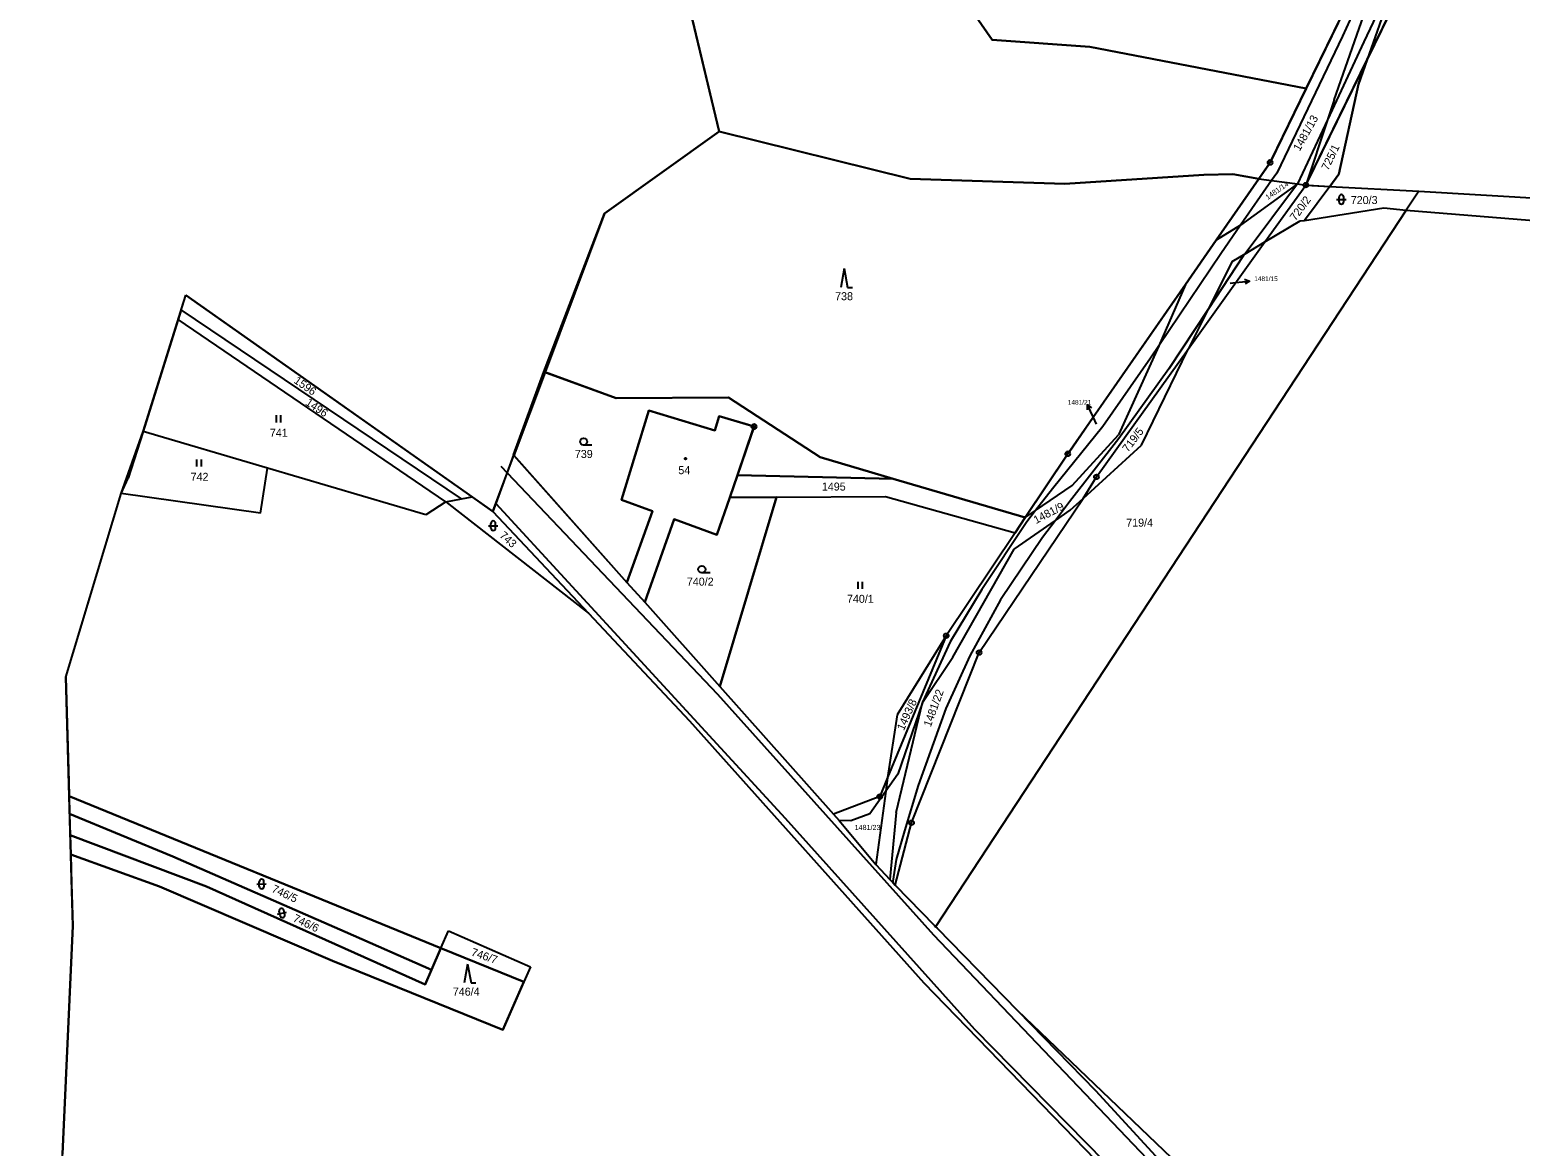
# Model space of a CAD drawing. Extents: x -760642 to -757221, y -1092371 to -1088855.
# Drawn here: x -760595.1 to -760278.5, y -1091176.2 to -1090939.2 of the extents above; entities that cross this region are included whole.
import ezdxf

# ---------------------------------------------------------------- set-up
doc = ezdxf.new("R2010")
doc.units = 0
for name, color, linetype in [('Vrstva 1', 7, 'Continuous'), ('Vrstva 13', 7, 'Continuous'), ('Vrstva 16', 7, 'Continuous'), ('Vrstva 18', 7, 'Continuous'), ('Vrstva 19', 7, 'Continuous'), ('Vrstva 24', 7, 'Continuous'), ('Vrstva 25', 7, 'Continuous'), ('Vrstva 28', 7, 'Continuous'), ('Vrstva 30', 7, 'Continuous'), ('Vrstva 4', 7, 'Continuous')]:
    doc.layers.add(name, color=color, linetype=linetype)

msp = doc.modelspace()

# ---------------------------------------------------------------- linework, layer by layer
at = {"layer": 'Vrstva 1'}
for p, q in [((-760308.9, -1090920.73), (-760324.01, -1090951.71)), ((-760318.08, -1090954.12), (-760305.91, -1090919.48)), ((-760303.79, -1090924.99), (-760311.05, -1090945.56)), ((-760311.05, -1090945.56), (-760301.6, -1090926.23)), ((-760395.84, -1090933.92), (-760390.7, -1090941.4)), ((-760390.7, -1090941.4), (-760369.95, -1090942.86)), ((-760369.95, -1090942.86), (-760324.01, -1090951.71)), ((-760324.09, -1090972.21), (-760311.05, -1090945.56)), ((-760311.05, -1090945.56), (-760312.89, -1090950.77)), ((-760324.01, -1090951.71), (-760331.67, -1090967.42)), ((-760312.89, -1090950.77), (-760317.05, -1090969.91)), ((-760318.08, -1090954.12), (-760319.48, -1090958.33)), ((-760319.48, -1090958.33), (-760324.09, -1090972.21)), ((-760448.69, -1090960.8), (-760408.07, -1090970.88)), ((-760331.67, -1090967.42), (-760334.08, -1090970.89)), ((-760408.07, -1090970.88), (-760375.23, -1090971.94)), ((-760375.23, -1090971.94), (-760345.74, -1090970.01)), ((-760345.74, -1090970.01), (-760339.59, -1090969.86)), ((-760334.08, -1090970.89), (-760343.1, -1090983.89)), ((-760339.59, -1090969.86), (-760334.08, -1090970.89)), ((-760325.86, -1090971.97), (-760337.93, -1090980.72)), ((-760334.08, -1090970.89), (-760331.36, -1090971.25)), ((-760331.36, -1090971.25), (-760325.86, -1090971.97)), ((-760325.86, -1090971.97), (-760324.09, -1090972.21)), ((-760317.05, -1090969.91), (-760318.97, -1090972.48)), ((-760332.74, -1090984.27), (-760324.09, -1090972.21)), ((-760318.97, -1090972.48), (-760324.37, -1090979.7)), ((-760324.09, -1090972.21), (-760318.97, -1090972.48)), ((-760318.97, -1090972.48), (-760300.1, -1090973.47)), ((-760300.1, -1090973.47), (-760302.77, -1090977.55)), ((-760300.1, -1090973.47), (-760272.54, -1090975.1)), ((-760302.77, -1090977.55), (-760402.7, -1091129.64)), ((-760324.37, -1090979.7), (-760307.48, -1090977.04)), ((-760307.48, -1090977.04), (-760302.77, -1090977.55)), ((-760302.77, -1090977.55), (-760270.4, -1090980.15)), ((-760337.93, -1090980.72), (-760343.1, -1090983.89)), ((-760332.74, -1090984.27), (-760325.28, -1090979.83)), ((-760325.28, -1090979.83), (-760324.37, -1090979.7)), ((-760343.1, -1090983.89), (-760349.65, -1090993.32)), ((-760349.06, -1091007.02), (-760332.74, -1090984.27)), ((-760336.96, -1090986.78), (-760332.74, -1090984.27)), ((-760339.71, -1090988.41), (-760336.96, -1090986.78)), ((-760339.71, -1090988.41), (-760344.87, -1090998.67)), ((-760349.65, -1090993.32), (-760374.62, -1091029.29)), ((-760349.65, -1090993.32), (-760355.28, -1091006.34)), ((-760503.4, -1091038.81), (-760562.9, -1090998.7)), ((-760344.87, -1090998.67), (-760349.06, -1091007.02)), ((-760506.69, -1091039.46), (-760563.55, -1091000.77)), ((-760355.28, -1091006.34), (-760363.82, -1091025.26)), ((-760368.53, -1091034.15), (-760349.06, -1091007.02)), ((-760358.95, -1091027.45), (-760349.06, -1091007.02)), ((-760485.91, -1091011.85), (-760470.52, -1091017.44)), ((-760470.52, -1091017.44), (-760446.7, -1091017.28)), ((-760446.7, -1091017.28), (-760427.2, -1091030)), ((-760463.63, -1091020.05), (-760469.4, -1091039.05)), ((-760449.58, -1091024.32), (-760463.63, -1091020.05)), ((-760448.65, -1091021.25), (-760449.58, -1091024.32)), ((-760441.26, -1091023.49), (-760448.65, -1091021.25)), ((-760544.55, -1091032.31), (-760571.02, -1091024.5)), ((-760441.26, -1091023.49), (-760444.78, -1091033.76)), ((-760373.66, -1091035.98), (-760363.82, -1091025.26)), ((-760371.37, -1091038.71), (-760358.95, -1091027.45)), ((-760492.35, -1091029.51), (-760468.24, -1091056.56)), ((-760427.2, -1091030), (-760411.7, -1091034.56)), ((-760374.62, -1091029.29), (-760383.66, -1091042.81)), ((-760546.06, -1091041.83), (-760544.55, -1091032.31)), ((-760510.92, -1091042.23), (-760544.55, -1091032.31)), ((-760444.78, -1091033.76), (-760446.42, -1091038.56)), ((-760444.78, -1091033.76), (-760411.7, -1091034.56)), ((-760411.7, -1091034.56), (-760383.66, -1091042.81)), ((-760371.37, -1091038.71), (-760368.53, -1091034.15)), ((-760546.06, -1091041.83), (-760575.65, -1091037.71)), ((-760503.4, -1091038.81), (-760501.13, -1091038.36)), ((-760436.47, -1091038.49), (-760448.53, -1091078.68)), ((-760446.42, -1091038.56), (-760436.47, -1091038.49)), ((-760436.47, -1091038.49), (-760413.36, -1091038.33)), ((-760413.36, -1091038.33), (-760385.79, -1091046)), ((-760381.47, -1091041.31), (-760373.66, -1091035.98)), ((-760506.69, -1091039.46), (-760510.92, -1091042.23)), ((-760506.69, -1091039.46), (-760503.4, -1091038.81)), ((-760506.69, -1091039.46), (-760476.43, -1091063.06)), ((-760496.71, -1091041.48), (-760476.43, -1091063.06)), ((-760469.4, -1091039.05), (-760462.84, -1091041.43)), ((-760462.84, -1091041.43), (-760468.24, -1091056.56)), ((-760446.42, -1091038.56), (-760449.12, -1091046.43)), ((-760393.47, -1091071.44), (-760371.37, -1091038.71)), ((-760383.66, -1091042.81), (-760381.47, -1091041.31)), ((-760377.23, -1091043.38), (-760374.15, -1091041.23)), ((-760374.15, -1091041.23), (-760371.37, -1091038.71)), ((-760458.18, -1091043.13), (-760464.48, -1091060.78)), ((-760458.18, -1091043.13), (-760449.12, -1091046.43)), ((-760385.98, -1091049.49), (-760377.23, -1091043.38)), ((-760383.66, -1091042.81), (-760385.79, -1091046)), ((-760385.79, -1091046), (-760400.43, -1091067.88)), ((-760399.03, -1091072.46), (-760385.98, -1091049.49)), ((-760468.24, -1091056.56), (-760464.48, -1091060.78)), ((-760476.43, -1091063.06), (-760454.93, -1091085.94)), ((-760464.48, -1091060.78), (-760448.53, -1091078.68)), ((-760400.43, -1091067.88), (-760412.88, -1091097.96)), ((-760400.43, -1091067.88), (-760410.85, -1091084.69)), ((-760407.81, -1091107.58), (-760393.47, -1091071.44)), ((-760405.51, -1091082.08), (-760399.03, -1091072.46)), ((-760448.53, -1091078.68), (-760424.37, -1091105.79)), ((-760411.08, -1091105.39), (-760405.51, -1091082.08)), ((-760454.93, -1091085.94), (-760405.18, -1091141.53)), ((-760410.85, -1091084.69), (-760412.88, -1091097.96)), ((-760412.88, -1091097.96), (-760414.57, -1091102.03)), ((-760412.88, -1091097.96), (-760413.27, -1091100.88)), ((-760413.27, -1091100.88), (-760415.37, -1091116.44)), ((-760586.71, -1091101.92), (-760507.74, -1091134.18)), ((-760414.57, -1091102.03), (-760424.37, -1091105.79)), ((-760564.71, -1091114.72), (-760586.6, -1091105.69)), ((-760424.37, -1091105.79), (-760423.19, -1091107.12)), ((-760423.19, -1091107.12), (-760415.37, -1091116.44)), ((-760411.08, -1091105.39), (-760412.39, -1091119.66)), ((-760411.28, -1091120.81), (-760407.81, -1091107.58)), ((-760586.48, -1091110.2), (-760557.56, -1091121.13)), ((-760567.52, -1091121.13), (-760586.36, -1091114.35)), ((-760564.71, -1091114.72), (-760528.07, -1091130.75)), ((-760415.37, -1091116.44), (-760412.39, -1091119.66)), ((-760412.39, -1091119.66), (-760411.81, -1091120.26)), ((-760411.81, -1091120.26), (-760411.28, -1091120.81)), ((-760530.75, -1091136.89), (-760567.52, -1091121.13)), ((-760557.56, -1091121.13), (-760511.12, -1091141.89)), ((-760411.28, -1091120.81), (-760402.9, -1091129.39)), ((-760402.9, -1091129.39), (-760402.7, -1091129.64)), ((-760402.7, -1091129.64), (-760402.34, -1091129.97)), ((-760402.34, -1091129.97), (-760385.31, -1091147.41)), ((-760528.07, -1091130.75), (-760509.75, -1091138.77)), ((-760507.74, -1091134.18), (-760506.14, -1091130.53)), ((-760506.14, -1091130.53), (-760488.73, -1091138.14)), ((-760509.75, -1091138.77), (-760507.74, -1091134.18)), ((-760507.74, -1091134.18), (-760490.14, -1091141.37)), ((-760494.58, -1091151.52), (-760530.75, -1091136.89)), ((-760509.75, -1091138.77), (-760511.12, -1091141.89)), ((-760488.73, -1091138.14), (-760490.14, -1091141.37)), ((-760490.14, -1091141.37), (-760494.58, -1091151.52)), ((-760405.18, -1091141.53), (-760373.22, -1091174.51)), ((-760334.03, -1091196.47), (-760385.31, -1091147.41)), ((-760385.31, -1091147.41), (-760368.71, -1091164.43)), ((-760368.71, -1091164.43), (-760338.69, -1091197.03)), ((-760373.22, -1091174.51), (-760347.55, -1091200.86))]:
    msp.add_line(p, q, dxfattribs=at)
at = {"layer": 'Vrstva 13'}
for p, q in [((-760464.43, -1090894.9), (-760448.69, -1090960.8)), ((-760473.02, -1090978.26), (-760448.69, -1090960.8)), ((-760485.91, -1091011.85), (-760473.02, -1090978.26)), ((-760562.9, -1090998.7), (-760561.91, -1090995.55)), ((-760501.13, -1091038.36), (-760561.91, -1090995.55)), ((-760562.9, -1090998.7), (-760563.55, -1091000.77)), ((-760563.55, -1091000.77), (-760571.02, -1091024.5)), ((-760492.35, -1091029.51), (-760485.91, -1091011.85)), ((-760571.02, -1091024.5), (-760574.15, -1091034.45)), ((-760492.35, -1091029.51), (-760496.1, -1091039.79)), ((-760575.65, -1091037.71), (-760574.15, -1091034.45)), ((-760584.51, -1091067.07), (-760575.65, -1091037.71)), ((-760496.71, -1091041.48), (-760501.13, -1091038.36)), ((-760496.1, -1091039.79), (-760496.71, -1091041.48)), ((-760587.4, -1091076.64), (-760584.51, -1091067.07)), ((-760587.4, -1091076.64), (-760586.79, -1091098.91)), ((-760586.79, -1091098.91), (-760586.71, -1091101.92)), ((-760586.71, -1091101.92), (-760586.6, -1091105.69)), ((-760586.6, -1091105.69), (-760586.48, -1091110.2)), ((-760586.48, -1091110.2), (-760586.46, -1091110.75)), ((-760586.46, -1091110.75), (-760586.36, -1091114.35)), ((-760586.36, -1091114.35), (-760586.19, -1091120.56)), ((-760586.19, -1091120.56), (-760585.95, -1091129.48)), ((-760585.95, -1091129.48), (-760588.15, -1091177.97))]:
    msp.add_line(p, q, dxfattribs=at)
at = {"layer": 'Vrstva 16'}
for p, q in [((-760340.15, -1090993.02), (-760339, -1090992.9)), ((-760339, -1090992.9), (-760336.016, -1090992.589)), ((-760369.17, -1091021.55), (-760370.435, -1091018.83)), ((-760368.5, -1091023), (-760369.17, -1091021.55))]:
    msp.add_line(p, q, dxfattribs=at)
for points in [[(-760337.063, -1090992.196), (-760336.016, -1090992.589), (-760336.959, -1090993.19)], [(-760370.467, -1091019.948), (-760370.435, -1091018.83), (-760369.56, -1091019.526)]]:
    msp.add_lwpolyline(points, dxfattribs=at)
at = {"layer": 'Vrstva 24'}
for centre, radius in [((-760331.67, -1090967.42), 0.5), ((-760331.67, -1090967.42), 0.0327), ((-760324.09, -1090972.21), 0.5), ((-760324.09, -1090972.21), 0.0327), ((-760441.26, -1091023.49), 0.5), ((-760441.26, -1091023.49), 0.0327), ((-760374.62, -1091029.29), 0.5), ((-760374.62, -1091029.29), 0.0327), ((-760368.53, -1091034.15), 0.5), ((-760368.53, -1091034.15), 0.0327), ((-760400.43, -1091067.88), 0.5), ((-760400.43, -1091067.88), 0.0327), ((-760393.47, -1091071.44), 0.5), ((-760393.47, -1091071.44), 0.0327), ((-760414.57, -1091102.03), 0.5), ((-760414.57, -1091102.03), 0.0327), ((-760407.81, -1091107.58), 0.5), ((-760407.81, -1091107.58), 0.0327)]:
    msp.add_circle(centre, radius, dxfattribs=at)
at = {"layer": 'Vrstva 25'}
for p, q in [((-760317.02, -1090975.74), (-760317.02, -1090974.74)), ((-760316.02, -1090975.74), (-760316.02, -1090974.74)), ((-760317.52, -1090975.24), (-760315.52, -1090975.24)), ((-760422.102, -1090989.939), (-760422.835, -1090993.939)), ((-760422.102, -1090989.939), (-760421.369, -1090993.939)), ((-760421.369, -1090993.939), (-760420.369, -1090993.939)), ((-760542.747, -1091021.085), (-760542.747, -1091022.585)), ((-760541.725, -1091022.585), (-760541.725, -1091021.085)), ((-760475.69, -1091027.44), (-760477.44, -1091027.44)), ((-760559.637, -1091030.445), (-760559.637, -1091031.945)), ((-760558.615, -1091031.945), (-760558.615, -1091030.445)), ((-760497.65, -1091044.52), (-760495.65, -1091044.52)), ((-760497.15, -1091045.02), (-760497.15, -1091044.02)), ((-760496.15, -1091045.02), (-760496.15, -1091044.02)), ((-760450.59, -1091054.54), (-760452.34, -1091054.54)), ((-760419.227, -1091056.455), (-760419.227, -1091057.955)), ((-760418.205, -1091057.955), (-760418.205, -1091056.455)), ((-760546.83, -1091120.611), (-760544.831, -1091120.57)), ((-760546.32, -1091121.1), (-760546.34, -1091120.101)), ((-760545.32, -1091121.08), (-760545.341, -1091120.08)), ((-760542.471, -1091126.957), (-760540.517, -1091126.529)), ((-760541.875, -1091127.338), (-760542.089, -1091126.362)), ((-760540.898, -1091127.125), (-760541.112, -1091126.148)), ((-760502.092, -1091137.569), (-760502.825, -1091141.569)), ((-760502.092, -1091137.569), (-760501.359, -1091141.569)), ((-760501.359, -1091141.569), (-760500.359, -1091141.569))]:
    msp.add_line(p, q, dxfattribs=at)
for centre, radius in [((-760477.44, -1091026.69), 0.75), ((-760455.81, -1091030.28), 0.175), ((-760452.34, -1091053.79), 0.75)]:
    msp.add_circle(centre, radius, dxfattribs=at)
for centre, start, end in [((-760316.52, -1090974.74), 0, 180), ((-760316.52, -1090975.74), 180, 0), ((-760496.65, -1091044.02), 0, 180), ((-760496.65, -1091045.02), 180, 0), ((-760545.841, -1091120.09), 1.16838, 181.16838), ((-760545.82, -1091121.09), 181.16838, 1.16838), ((-760541.601, -1091126.255), 12.33936, 192.33936), ((-760541.387, -1091127.232), 192.33936, 12.33936)]:
    msp.add_arc(centre, 0.5, start, end, dxfattribs=at)
at = {"layer": 'Vrstva 28'}
for points in [[(-760561.91, -1090995.55), (-760496.71, -1091041.48), (-760473.02, -1090978.26), (-760448.69, -1090960.8), (-760464.43, -1090894.9)], [(-760573.63, -1091420.31), (-760585.78, -1091349.95), (-760595.06, -1091293.72), (-760595.06, -1091293.72), (-760591.68, -1091230.75), (-760589.05, -1091197.58), (-760588.15, -1091177.97), (-760585.95, -1091129.48), (-760586.71, -1091101.92), (-760587.4, -1091076.64), (-760575.65, -1091037.71), (-760571.02, -1091024.5), (-760561.91, -1090995.55)]]:
    msp.add_lwpolyline(points, dxfattribs=at)
at = {"layer": 'Vrstva 30'}
for points in [[(-760483.933, -1090718.246), (-760508.9, -1090733.95), (-760505.34, -1090744.7), (-760502.31, -1090767.43), (-760480.317, -1090839.289), (-760478.97, -1090843.69), (-760473.37, -1090865.91), (-760464.43, -1090894.9), (-760448.69, -1090960.8), (-760408.07, -1090970.88), (-760375.23, -1090971.94), (-760345.74, -1090970.01), (-760339.59, -1090969.86), (-760334.08, -1090970.89), (-760331.955, -1090967.831)], [(-760301.82, -1090926.679), (-760311.05, -1090945.56), (-760312.89, -1090950.77), (-760317.05, -1090969.91), (-760318.97, -1090972.48), (-760300.1, -1090973.47), (-760272.54, -1090975.1), (-760240.96, -1090967.57), (-760199.02, -1090950.37), (-760175.7, -1090935.99), (-760191.82, -1090920.28), (-760209.38, -1090903.18), (-760217.46, -1090912.68), (-760240.32, -1090877.27), (-760234.76, -1090873.85), (-760250.43, -1090857.2), (-760274.06, -1090892.106)], [(-760395.84, -1090933.92), (-760390.7, -1090941.4), (-760369.95, -1090942.86), (-760324.01, -1090951.71), (-760309.119, -1090921.179)], [(-760331.451, -1090966.971), (-760324.01, -1090951.71), (-760369.95, -1090942.86), (-760390.7, -1090941.4), (-760395.84, -1090933.92)], [(-760323.591, -1090972.236), (-760318.97, -1090972.48), (-760317.05, -1090969.91), (-760312.89, -1090950.77), (-760311.05, -1090945.56), (-760323.87, -1090971.761)], [(-760374.335, -1091028.879), (-760369.201, -1091021.484), (-760349.65, -1090993.32), (-760343.1, -1090983.89), (-760334.08, -1090970.89), (-760339.59, -1090969.86), (-760345.74, -1090970.01), (-760375.23, -1090971.94), (-760408.07, -1090970.88), (-760448.69, -1090960.8), (-760473.02, -1090978.26), (-760485.643, -1091011.947), (-760470.52, -1091017.44), (-760446.7, -1091017.28), (-760427.2, -1091030), (-760411.7, -1091034.56), (-760383.66, -1091042.81), (-760374.898, -1091029.706)], [(-760441.422, -1091023.963), (-760444.78, -1091033.76), (-760411.7, -1091034.56), (-760427.2, -1091030), (-760446.7, -1091017.28), (-760470.52, -1091017.44), (-760485.643, -1091011.947), (-760492.262, -1091029.609), (-760468.24, -1091056.56), (-760462.84, -1091041.43), (-760469.4, -1091039.05), (-760463.63, -1091020.05), (-760449.58, -1091024.32), (-760448.65, -1091021.25), (-760441.739, -1091023.345)], [(-760441.739, -1091023.345), (-760448.65, -1091021.25), (-760449.58, -1091024.32), (-760463.63, -1091020.05), (-760469.4, -1091039.05), (-760462.84, -1091041.43), (-760468.24, -1091056.56), (-760464.48, -1091060.78), (-760458.18, -1091043.13), (-760449.12, -1091046.43), (-760446.42, -1091038.56), (-760444.78, -1091033.76), (-760441.422, -1091023.963)], [(-760411.7, -1091034.56), (-760444.78, -1091033.76), (-760446.42, -1091038.56), (-760436.47, -1091038.49), (-760413.36, -1091038.33), (-760385.79, -1091046), (-760383.66, -1091042.81), (-760411.7, -1091034.56)], [(-760448.53, -1091078.68), (-760436.47, -1091038.49), (-760446.42, -1091038.56), (-760449.12, -1091046.43), (-760458.18, -1091043.13), (-760464.48, -1091060.78), (-760448.53, -1091078.68)], [(-760507.74, -1091134.18), (-760586.71, -1091101.92), (-760586.6, -1091105.69), (-760564.71, -1091114.72), (-760528.07, -1091130.75), (-760509.75, -1091138.77), (-760507.74, -1091134.18)], [(-760509.75, -1091138.77), (-760528.07, -1091130.75), (-760564.71, -1091114.72), (-760586.6, -1091105.69), (-760586.48, -1091110.2), (-760557.56, -1091121.13), (-760511.12, -1091141.89), (-760509.75, -1091138.77)], [(-760586.482, -1091110.2), (-760586.367, -1091114.35), (-760586.36, -1091114.35), (-760567.52, -1091121.13), (-760530.75, -1091136.89), (-760494.58, -1091151.52), (-760490.14, -1091141.37), (-760507.74, -1091134.18), (-760509.75, -1091138.77), (-760511.12, -1091141.89), (-760557.56, -1091121.13), (-760586.48, -1091110.2), (-760586.482, -1091110.2)]]:
    msp.add_lwpolyline(points, dxfattribs=at)
for centre, start, end in [((-760331.67, -1090967.42), 64.00671, 180), ((-760331.67, -1090967.42), 180, 235.21907), ((-760324.09, -1090972.21), 0, 63.92723), ((-760324.09, -1090972.21), 356.98134, 0), ((-760441.26, -1091023.49), 163.1373, 180), ((-760441.26, -1091023.49), 180, 251.08106), ((-760441.26, -1091023.49), 0, 163.1373), ((-760441.26, -1091023.49), 251.08106, 0), ((-760374.62, -1091029.29), 55.23202, 180), ((-760374.62, -1091029.29), 180, 236.23177)]:
    msp.add_arc(centre, 0.5, start, end, dxfattribs=at)
at = {"layer": 'Vrstva 4'}
for p, q in [((-760307.85, -1090922.07), (-760316.26, -1090940.59)), ((-760303.79, -1090924.99), (-760311.75, -1090941.81)), ((-760316.26, -1090940.59), (-760330.26, -1090969.66)), ((-760311.75, -1090941.81), (-760319.48, -1090958.33)), ((-760319.48, -1090958.33), (-760325.86, -1090971.97)), ((-760331.36, -1090971.25), (-760337.93, -1090980.72)), ((-760325.86, -1090971.97), (-760336.96, -1090986.78)), ((-760330.26, -1090969.66), (-760331.36, -1090971.25)), ((-760337.93, -1090980.72), (-760342.15, -1090986.79)), ((-760342.15, -1090986.79), (-760355.28, -1091006.34)), ((-760337.27, -1090987.19), (-760344.87, -1090998.67)), ((-760336.96, -1090986.78), (-760337.27, -1090987.19)), ((-760344.87, -1090998.67), (-760353.16, -1091011.21)), ((-760355.28, -1091006.34), (-760357.04, -1091008.95)), ((-760357.04, -1091008.95), (-760367.18, -1091023.45)), ((-760353.16, -1091011.21), (-760363.79, -1091025.99)), ((-760367.18, -1091023.45), (-760377.87, -1091036.66)), ((-760363.79, -1091025.99), (-760374.25, -1091039.42)), ((-760495.06, -1091031.89), (-760449.04, -1091080.28)), ((-760377.87, -1091036.66), (-760381.47, -1091041.31)), ((-760496.1, -1091039.79), (-760434.62, -1091106.62)), ((-760381.47, -1091041.31), (-760383.3, -1091043.68)), ((-760374.25, -1091039.42), (-760377.23, -1091043.38)), ((-760383.3, -1091043.68), (-760392.87, -1091058.09)), ((-760377.23, -1091043.38), (-760379.96, -1091047.01)), ((-760379.96, -1091047.01), (-760388.92, -1091060.28)), ((-760392.87, -1091058.09), (-760399.6, -1091069.18)), ((-760388.92, -1091060.28), (-760395.45, -1091072.12)), ((-760399.6, -1091069.18), (-760405.47, -1091082)), ((-760395.45, -1091072.12), (-760400.54, -1091083.3)), ((-760449.04, -1091080.28), (-760403.15, -1091131.37)), ((-760405.51, -1091082.08), (-760410.72, -1091097.3)), ((-760405.47, -1091082), (-760405.51, -1091082.08)), ((-760400.54, -1091083.3), (-760406.39, -1091099.7)), ((-760410.72, -1091097.3), (-760413.27, -1091100.88)), ((-760413.27, -1091100.88), (-760416.68, -1091105.66)), ((-760406.39, -1091099.7), (-760409.3, -1091109.33)), ((-760434.62, -1091106.62), (-760394.44, -1091151.43)), ((-760420.7, -1091107.18), (-760423.19, -1091107.12)), ((-760416.68, -1091105.66), (-760420.7, -1091107.18)), ((-760409.3, -1091109.33), (-760411.1, -1091115.39)), ((-760411.1, -1091115.39), (-760411.77, -1091120.01)), ((-760411.77, -1091120.01), (-760411.81, -1091120.26)), ((-760403.15, -1091131.37), (-760341.27, -1091196.2)), ((-760394.44, -1091151.43), (-760346.69, -1091199.91))]:
    msp.add_line(p, q, dxfattribs=at)

# ---------------------------------------------------------------- texts
at = {"layer": 'Vrstva 16'}
for s, p in [('1481/15', (-760335.02, -1090992.59)), ('1481/21', (-760374.625, -1091018.83))]:
    msp.add_text(s, height=1, dxfattribs=at).set_placement(p)
at = {"layer": 'Vrstva 18'}
for s, height, rotation, p in [('1481/13', 1.7, 60.71859, (-760325.375, -1090965.147)), ('725/1', 1.7, 64.11969, (-760319.33, -1090969.22)), ('1481/14', 1.1, 34.72866, (-760332.152, -1090975.379)), ('720/2', 1.7, 53.63082, (-760326.25, -1090979.93)), ('1596', 1.7, 325.07433, (-760539.124, -1091014.077)), ('1496', 1.7, 326.30994, (-760536.675, -1091018.757)), ('719/5', 1.7, 52.4988, (-760361.85, -1091029.04)), ('1481/9', 1.7, 27.68562, (-760381.36, -1091044.18)), ('743', 1.7, 317.79567, (-760495.438, -1091046.784)), ('1481/22', 1.7, 70.09245, (-760403.719, -1091087.359)), ('1493/8', 1.7, 65.889, (-760409.44, -1091088.14)), ('746/5', 1.7, 334.78992, (-760543.84, -1091122.19)), ('746/6', 1.7, 334.66572, (-760539.32, -1091128.44)), ('746/7', 1.7, 341.17533, (-760501.47, -1091135.73))]:
    msp.add_text(s, height=height, rotation=rotation, dxfattribs=at).set_placement(p)
for s, height, p in [('720/3', 1.7, (-760314.52, -1090976.24)), ('1481/15', 0.1, (-760340.308, -1090993.02)), ('738', 1.7, (-760424.033, -1090996.65)), ('741', 1.7, (-760544.08, -1091025.64)), ('1481/21', 0.1, (-760368.659, -1091023)), ('739', 1.7, (-760479.306, -1091030.14)), ('742', 1.7, (-760560.91, -1091034.99)), ('1495', 1.7, (-760426.846, -1091037.06)), ('719/4', 1.7, (-760362.21, -1091044.72)), ('740/2', 1.7, (-760455.522, -1091057.24)), ('740/1', 1.7, (-760421.52, -1091060.89)), ('1481/23', 1.1, (-760419.888, -1091109.13)), ('746/4', 1.7, (-760505.224, -1091144.28))]:
    msp.add_text(s, height=height, dxfattribs=at).set_placement(p)
at = {"layer": 'Vrstva 19'}
msp.add_text('54', height=1.7, dxfattribs=at).set_placement((-760457.328, -1091033.58))

doc.saveas('drawing.dxf')
